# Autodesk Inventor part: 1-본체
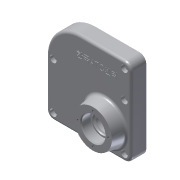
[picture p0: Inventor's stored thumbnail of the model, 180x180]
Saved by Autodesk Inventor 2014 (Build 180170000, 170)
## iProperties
Created: 2015-11
Part Number: 1-본체
Material: 알루미늄 6061
Document SubType Name: Modeling
Designer: SURY
Density: 2.71 g/cm^3
Appearance: 알루미늄 - 평지
Mass: 247.549 g
Surface Area: 389.441 cm^2
Volume: 91.3466 cm^3
Author: SURY
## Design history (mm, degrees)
sketch "스케치1"
  geometry: L1 (-50, 51.5)-(10, 51.5); L2 (50, 11.5)-(50, -51.5); L3 (50, -51.5)-(-50, -51.5); L4 (-50, -51.5)-(-50, 51.5); L5 (10, 47.5)-(-46, 47.5); L6 (-46, 47.5)-(-46, -47.5); L7 (-46, -47.5)-(46, -47.5); L8 (46, -47.5)-(46, 11.5); C1 r 6 at (-42, 43.5); C2 r 6 at (42, 11.5); C3 r 6 at (42, -43.5); C4 r 6 at (-42, -43.5); C5 r 6 at (-42, 11.5); A1 r 40 centre (10, 11.5) between (50, 11.5) and (10, 51.5); A2 r 36 centre (10, 11.5) between (46, 11.5) and (10, 47.5); 2 further points
  constraints: 16 end point, 7 centre point, 4 equal radius, 4 parallel, 4 point on circle, 3 vertical alignment, 2 horizontal alignment, 2 perpendicular, 1 horizontal, 1 midpoint, 1 tangent, 4 other
  dimensions: "d0" = 12 diameter of C1; "d1" = 100 distance between parallel lines of L2 L4; "d2" = 103 distance of L3.end L1.start; "d3" = 63 distance from line of L3 C5.centre; "d4" = 8 distance from line of L3 C3.centre; "d5" = 55 distance of C3.centre C2.centre; "d6" = 32 vertical distance of C1.centre C2.centre; "d7" = 84 horizontal distance of C2.centre C1.centre; "d8" = 42 horizontal distance of C1.centre point (0, 0); "d9" = 50 distance from line of L4 point (0, 0); "d10" = 40 radius of A1; "d12" = 60 distance from line of L4 A1.centre; "d13" = 36 radius of A2; "d14" = 4 distance between parallel lines of L3 L7 (derived)
extrude "돌출1" new body sketch "스케치1" distance "d15" = 18; taper "d16" = 0 deg
extrude "돌출2" cut sketch "스케치1" distance "d17" = 14; taper "d18" = 0 deg
extrude "돌출3" join sketch "스케치1" distance "d19" = 14; taper "d20" = 0 deg
sketch "스케치2"
  geometry: L1 (-50, 51.5)-(50, 51.5) reference; L2 (50, 51.5)-(50, -51.5) reference; C1 r 20 at (20, 21.5); C2 r 20 at (-10, -11.5); 1 further point
  constraints: 2 centre point
  dimensions: "d21" = 40 diameter of C2; "d22" = 40 diameter of C1; "d23" = 63 distance from line of L1 C2.centre; "d24" = 60 distance from line of L2 C2.centre; "d25" = 30 distance from line of L2 C1.centre; "d26" = 30 distance from line of L1 C1.centre
extrude "돌출4" join sketch "스케치2" distance "d27" = 11; taper "d28" = -10 deg
sketch "스케치3"
  geometry: L1 (50, -51.5)-(50, 51.5) reference; L2 (-50, -51.5)-(50, -51.5) reference; C1 r 25 at (20, -21.5); 1 further point
  constraints: 1 centre point
  dimensions: "d29" = 30 distance from line of L1 C1.centre; "d30" = 30 distance from line of C1.centre L2; "d31" = 50 diameter of C1
extrude "돌출5" join sketch "스케치3" distance "d32" = 15; taper "d33" = -10 deg
fillet "모깎기1" dims "d34" = 8, "d35" = 3
sketch "스케치4"
  geometry: C1 r 18.06 at (30, 33) reference; C2 r 18.06 at (0, 0) reference; 3 further points
  constraints: 2 coincident
  node "투영된 루프1"
  node "투영된 루프2"
hole "구멍1" diameter "d38" = 20; stored, may be unused: countersink angle "d42" = 90 deg, drill point angle "d44" = 118 deg; dims "d36" = 10, "d37" = 10, "d39" = 6, "d40" = 32, "d41" = 9, "d43" = 8
hole "구멍2" diameter "d47" = 22; stored, may be unused: countersink angle "d51" = 90 deg, drill point angle "d53" = 0 deg; dims "d45" = 10, "d46" = 10, "d48" = 6, "d49" = 32, "d50" = 9, "d52" = 2
sketch "스케치5"
  geometry: C1 r 10 at (0, 0) reference; C2 r 22.355 at (0, 0) reference; 2 further points
  constraints: 1 coincident
  node "투영된 루프3"
hole "구멍3" diameter "d56" = 24; stored, may be unused: countersink angle "d60" = 90 deg, drill point angle "d62" = 0 deg; dims "d54" = 10, "d55" = 10, "d57" = 6, "d58" = 28, "d59" = 11, "d61" = 2
fillet "모깎기2" dims "d63" = 0.3, "d64" = 3
chamfer "모따기1" distance "d65" = 1; stored, may be unused: second distance "d66" = 2, angle "d67" = 45 deg
sketch "스케치6"
  geometry: L1 (50, -43.5)-(50, 43.5) reference; L2 (-42, -51.5)-(42, -51.5) reference; 6 further points
  constraints: 3 vertical alignment, 2 horizontal alignment
  dimensions: "d72" = 8 distance from line of point (-42, -43.5) L2; "d73" = 55 distance of point (-42, -43.5) point (-42, 11.5); "d74" = 32 vertical distance of point (-42, 11.5) point (42, 43.5); "d75" = 84 horizontal distance of point (-42, 11.5) point (42, 43.5); "d76" = 42 horizontal distance of point (-42, 11.5) point (0, 0)
hole "구멍4" sketch "스케치6" at (-42, -43.5), (-42, 11.5), (42, -43.5), (42, 43.5), (42, 11.5) diameter "d77" = 4.5; stored, may be unused: countersink angle "d81" = 90 deg, drill point angle "d83" = 0 deg; dims "d78" = 6, "d79" = 8, "d80" = 4.4, "d82" = 2
sketch "스케치7" dims "d84" = 36
  geometry: L1 (30, -22)-(30, 65) reference; L2 (-62, -30)-(22, -30) reference; 3 further points
  constraints: 2 vertical alignment, 2 other
  dimensions: "d85" = 30 distance from line of L1 point (0, 0); "d86" = 30 distance from line of L2 point (0, 0)
hole "구멍5" sketch "스케치7" at (0, 18) diameter "d87" = 2.459; stored, may be unused: countersink angle "d91" = 90 deg, drill point angle "d93" = 118 deg; dims "d88" = 8, "d89" = 32, "d90" = 9, "d92" = 10
sketch "스케치8"
  geometry: L1 (-14.887, 35.102)-(34.887, 35.102); L2 (34.887, 35.102)-(34.887, 27.898); L3 (34.887, 27.898)-(-14.887, 27.898); L4 (-14.887, 27.898)-(-14.887, 35.102); L5 (-14.887, 31.5)-(34.887, 31.5); L6 (10, 35.102)-(10, 27.898); L7 (42, 51.5)-(-10, 51.5) reference; L8 (50, -43.5)-(50, 43.5) reference; 2 further points
  constraints: 5 midpoint, 4 end point, 2 other
  dimensions: "d97" = 20 distance from line of point (10, 31.5) L7; "d98" = 40 distance from line of point (10, 31.5) L8
feature "엠보싱1" sketch "스케치8" dims "d0" = 12, "d1" = 100, "d2" = 103, "d3" = 63, "d4" = 8, "d5" = 55, "d6" = 32, "d7" = 84, "d8" = 42, "d9" = 50, "d10" = 40, "d12" = 60, "d13" = 36, "d14" = 4 (derived), "d99" = 0.5, "d100" = 0
node "솔리드1"
pattern_circular "원형 패턴1" dims angle "d95" = 360 deg
